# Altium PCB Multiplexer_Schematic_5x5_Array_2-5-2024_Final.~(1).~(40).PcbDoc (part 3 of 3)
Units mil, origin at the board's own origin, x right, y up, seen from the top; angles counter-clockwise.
Board outline 7305 x 4000 mil, 8 copper layers (Loop Shield 1, Loop Trace, Loop Shield 2, GND 1, DC Signal 1, DC Signal 2, GND 2 (RF), RF), stack 74.018 mil thick; 89 components, 122 nets, 436 pads, 3654 vias.
Unrouted connection lines stored in the file: 2.
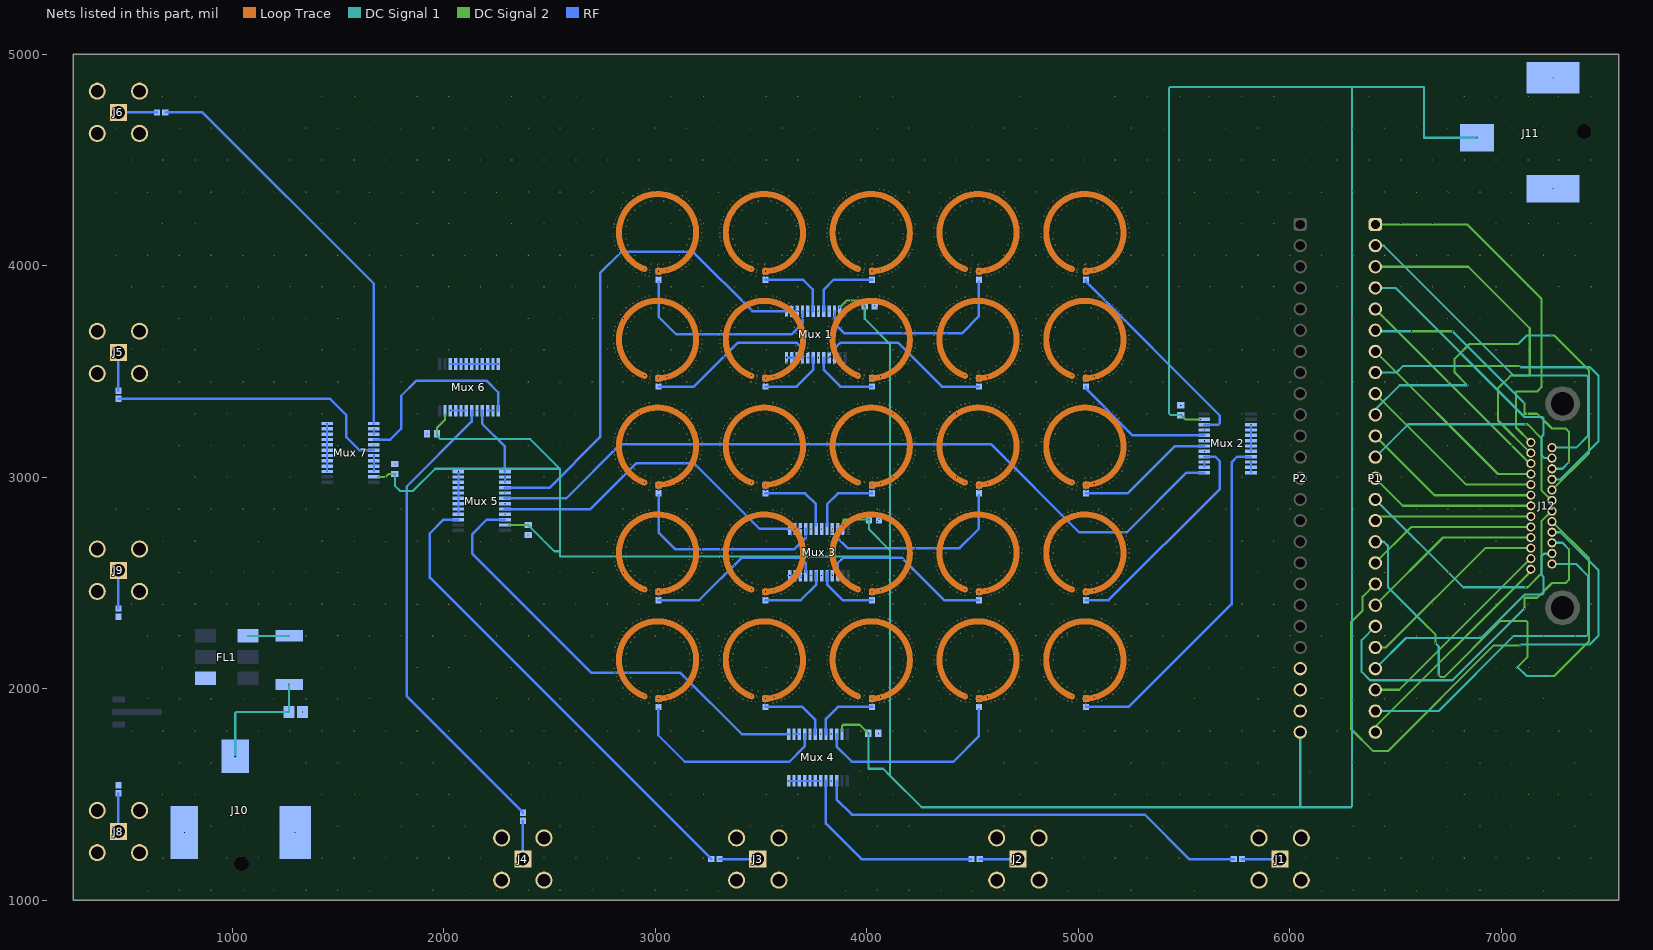
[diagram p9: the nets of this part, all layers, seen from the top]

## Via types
v1: diameter 6, hole 4, Loop Shield 1 to Loop Shield 2, 2300 vias
v2: diameter 6, hole 4, GND 2 (RF) to RF, 1131 vias
v3: diameter 6, hole 4, Loop Shield 2 to RF, 75 vias
v4: diameter 6, hole 4, DC Signal 1 to DC Signal 2, 57 vias
v5: diameter 6, hole 4, DC Signal 1 to RF, 25 vias
v6: diameter 6, hole 4, Loop Shield 2 to GND 2 (RF), 25 vias
v7: diameter 6, hole 4, Loop Trace to RF, 25 vias
v8: diameter 6, hole 4, DC Signal 2 to RF, 16 vias

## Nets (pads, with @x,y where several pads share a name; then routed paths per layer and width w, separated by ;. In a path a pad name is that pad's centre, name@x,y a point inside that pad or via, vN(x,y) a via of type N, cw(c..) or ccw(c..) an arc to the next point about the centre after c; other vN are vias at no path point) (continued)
GND: (continued)
  other v2: 450,1050 600,1050 750,1050 900,1050 1050,1050 1200,1050 1350,1050 1500,1050 1650,1050 1800,1050 1950,1050 2100,1050 2250,1050 2400,1050 2550,1050 2700,1050 2850,1050 3000,1050 3150,1050 3300,1050 3450,1050 3750,1050 3900,1050 4050,1050 4200,1050 4350,1050 4500,1050 4650,1050 4950,1050 5100,1050 5250,1050 5400,1050 5550,1050 5700,1050 6000,1050 6150,1050 6300,1050 6450,1050 6600,1050 6750,1050 6900,1050 7050,1050 7200,1050 7350,1050 675,1200 975,1200 1125,1200 1425,1200 1575,1200 1725,1200 1875,1200 2025,1200 2175,1200 2475,1200 2625,1200 2775,1200 2925,1200 3075,1200 3225,1200 3675,1200 3825,1200 4875,1200 5025,1200 5175,1200 5325,1200 5475,1200 6075,1200 6225,1200 6375,1200 6525,1200 6675,1200 6825,1200 6975,1200 7125,1200 7275,1200 7425,1200 774.92,1320.71 1298.15,1320.71 600,1350 900,1350 1050,1350 1200,1350 1500,1350 1650,1350 1800,1350 1950,1350 2100,1350 2250,1350 2550,1350 2700,1350 2850,1350 3000,1350 3150,1350 3300,1350 3450,1350 3600,1350 3750,1350 3900,1350 4050,1350 4200,1350 4350,1350 4500,1350 4650,1350 4800,1350 4950,1350 5100,1350 5250,1350 5400,1350 5550,1350 5700,1350 5850,1350 6000,1350 6150,1350 6300,1350 6450,1350 6600,1350 6750,1350 6900,1350 7050,1350 7200,1350 7350,1350 525,1500 675,1500 825,1500 975,1500 1125,1500 1275,1500 1425,1500 1575,1500 1725,1500 1875,1500 2025,1500 2175,1500 2325,1500 2475,1500 2625,1500 2775,1500 2925,1500 3075,1500 3225,1500 3375,1500 3525,1500 3675,1500 3975,1500 4125,1500 4275,1500 4425,1500 4575,1500 4725,1500 4875,1500 5025,1500 5175,1500 5325,1500 5475,1500 5625,1500 5775,1500 5925,1500 6075,1500 6225,1500 6375,1500 6525,1500 6675,1500 6825,1500 6975,1500 7125,1500 7275,1500 7425,1500 3832.99,1564.76 600,1650 750,1650 900,1650 1200,1650 1350,1650 1500,1650 1650,1650 1800,1650 1950,1650 2100,1650 2250,1650 2400,1650 2550,1650 2700,1650 2850,1650 3000,1650 3750,1650 3900,1650 4500,1650 4650,1650 4800,1650 4950,1650 5100,1650 5250,1650 5400,1650 5550,1650 5700,1650 5850,1650 6000,1650 6150,1650 6300,1650 6450,1650 6600,1650 6750,1650 6900,1650 7050,1650 7200,1650 7350,1650 3656.61,1785.24 3732.2,1785.24 3782.6,1785.24 3832.99,1785.24 4055.51,1788.62 525,1800 675,1800 825,1800 975,1800 1125,1800 1275,1800 1425,1800 1575,1800 1725,1800 1875,1800 2025,1800 2175,1800 2325,1800 2475,1800 2625,1800 2775,1800 2925,1800 3075,1800 3225,1800 3975,1800 4125,1800 4275,1800 4425,1800 4575,1800 4725,1800 4875,1800 5025,1800 5175,1800 5325,1800 5475,1800 5625,1800 5775,1800 5925,1800 6225,1800 6525,1800 6675,1800 6825,1800 6975,1800 7125,1800 7275,1800 7425,1800 1333.45,1890 600,1950 750,1950 900,1950 1050,1950 1200,1950 1350,1950 1500,1950 1650,1950 1800,1950 1950,1950 2100,1950 2250,1950 2400,1950 2550,1950 2700,1950 2850,1950 3150,1950 3300,1950 3450,1950 3600,1950 3750,1950 3900,1950 4200,1950 4350,1950 4650,1950 4800,1950 4950,1950 5100,1950 5400,1950 5550,1950 5700,1950 5850,1950 6000,1950 6150,1950 6300,1950 6450,1950 6600,1950 6750,1950 6900,1950 7050,1950 7200,1950 7350,1950 525,2100 675,2100 825,2100 975,2100 1125,2100 1275,2100 1425,2100 1575,2100 1725,2100 1875,2100 2025,2100 2175,2100 2325,2100 2475,2100 2625,2100 2775,2100 2925,2100 3075,2100 3225,2100 3375,2100 3525,2100 3675,2100 3825,2100 3975,2100 4125,2100 4275,2100 4425,2100 4575,2100 4725,2100 4875,2100 5025,2100 5175,2100 5325,2100 5475,2100 5625,2100 5775,2100 5925,2100 6225,2100 6525,2100 6675,2100 6825,2100 6975,2100 7125,2100 7275,2100 7425,2100 600,2250 750,2250 1350,2250 1500,2250 1650,2250 1800,2250 1950,2250 2100,2250 2250,2250 2400,2250 2700,2250 2850,2250 3000,2250 3150,2250 3300,2250 3450,2250 3600,2250 3750,2250 3900,2250 4050,2250 4200,2250 4350,2250 4500,2250 4650,2250 4800,2250 4950,2250 5100,2250 5250,2250 5400,2250 5700,2250 5850,2250 6000,2250 6150,2250 6300,2250 6450,2250 6600,2250 6750,2250 6900,2250 7050,2250 7200,2250 7350,2250 525,2400 675,2400 825,2400 975,2400 1125,2400 1275,2400 1425,2400 1575,2400 1725,2400 1875,2400 2025,2400 2175,2400 2325,2400 2475,2400 2625,2400 2775,2400 2925,2400 3225,2400 3375,2400 3825,2400 4125,2400 4275,2400 4575,2400 4725,2400 4875,2400 5175,2400 5325,2400 5475,2400 5625,2400 5775,2400 5925,2400 6225,2400 6525,2400 6675,2400 6825,2400 6975,2400 7125,2400 7425,2400 3737.2,2534.76 3787.6,2534.76 3837.99,2534.76 600,2550 750,2550 900,2550 1050,2550 1200,2550 1350,2550 1500,2550 1650,2550 1800,2550 2100,2550 2400,2550 2550,2550 2700,2550 2850,2550 3000,2550 3150,2550 3300,2550 3450,2550 3600,2550 4050,2550 4200,2550 4350,2550 4500,2550 4650,2550 4800,2550 4950,2550 5100,2550 5400,2550 5550,2550 5700,2550 5850,2550 6000,2550 6150,2550 6300,2550 6450,2550 6600,2550 6750,2550 6900,2550 7050,2550 7200,2550 7350,2550 525,2700 675,2700 825,2700 975,2700 1125,2700 1275,2700 1425,2700 1575,2700 1725,2700 1875,2700 2025,2700 2175,2700 2325,2700 2475,2700 2625,2700 2775,2700 2925,2700 3225,2700 3375,2700 3525,2700 3825,2700 3975,2700 4125,2700 4275,2700 4425,2700 4575,2700 4725,2700 4875,2700 5025,2700 5175,2700 5325,2700 5475,2700 5625,2700 5775,2700 5925,2700 6225,2700 6525,2700 6675,2700 6825,2700 6975,2700 7275,2700 7425,2700 2400,2726.38 3737.2,2755.24 3787.6,2755.24 3837.99,2755.24 4058.62,2800 2290.24,2824.38 450,2850 600,2850 750,2850 900,2850 1050,2850 1200,2850 1350,2850 1500,2850 1650,2850 1800,2850 1950,2850 2850,2850 3150,2850 3300,2850 3450,2850 3600,2850 3900,2850 4050,2850 4200,2850 4350,2850 4500,2850 4650,2850 4800,2850 4950,2850 5100,2850 5250,2850 5400,2850 5700,2850 5850,2850 6000,2850 6150,2850 6300,2850 6450,2850 6600,2850 6750,2850 6900,2850 7050,2850 7200,2850 7350,2850 2290.24,2874.77 2290.24,2925.17 525,3000 675,3000 825,3000 975,3000 1125,3000 1275,3000 1575,3000 1725,3000 2025,3000 2175,3000 2475,3000 2625,3000 2775,3000 2925,3000 3075,3000 3375,3000 3675,3000 3825,3000 3975,3000 4125,3000 4275,3000 4425,3000 4575,3000 4875,3000 5175,3000 5625,3000 5775,3000 5925,3000 6225,3000 6525,3000 6675,3000 6825,3000 6975,3000 7275,3000 7425,3000 1770,3062.24 5596.47,3122.2 450,3150 600,3150 750,3150 900,3150 1050,3150 1200,3150 1350,3150 1500,3150 1800,3150 1950,3150 2100,3150 2250,3150 2400,3150 2550,3150 4650,3150 4800,3150 4950,3150 5100,3150 5250,3150 5400,3150 5700,3150 6000,3150 6150,3150 6300,3150 6450,3150 6600,3150 6750,3150 6900,3150 7050,3150 7200,3150 7350,3150 1670.24,3152.8 5596.47,3172.6 1921.38,3205 5596.47,3222.99 525,3300 675,3300 825,3300 975,3300 1125,3300 1275,3300 1425,3300 1575,3300 1725,3300 1875,3300 2325,3300 2475,3300 2625,3300 2775,3300 2925,3300 3075,3300 3225,3300 3375,3300 3525,3300 3675,3300 3825,3300 3975,3300 4125,3300 4275,3300 4425,3300 4575,3300 4725,3300 4875,3300 5025,3300 5325,3300 5775,3300 5925,3300 6225,3300 6525,3300 6675,3300 6825,3300 6975,3300 7125,3300 7425,3300 2157.8,3314.76 5485,3340 600,3450 750,3450 900,3450 1050,3450 1200,3450 1350,3450 1500,3450 1650,3450 1800,3450 2250,3450 2400,3450 2550,3450 2700,3450 2850,3450 3150,3450 3300,3450 3450,3450 3600,3450 3750,3450 3900,3450 4200,3450 4650,3450 4800,3450 4950,3450 5100,3450 5250,3450 5400,3450 5550,3450 5700,3450 5850,3450 6000,3450 6150,3450 6300,3450 6450,3450 6600,3450 6750,3450 6900,3450 7050,3450 7200,3450 7350,3450 2258.58,3535.52 3722.2,3564.76 3772.6,3564.76 3822.99,3564.76 525,3600 675,3600 825,3600 975,3600 1125,3600 1275,3600 1425,3600 1575,3600 1725,3600 1875,3600 2025,3600 2175,3600 2325,3600 2475,3600 2625,3600 2775,3600 2925,3600 3075,3600 3225,3600 3525,3600 3975,3600 4125,3600 4275,3600 4425,3600 4575,3600 4725,3600 4875,3600 5025,3600 5175,3600 5325,3600 5475,3600 5625,3600 5775,3600 5925,3600 6225,3600 6525,3600 6675,3600 6825,3600 6975,3600 7125,3600 7275,3600 7425,3600 450,3750 600,3750 750,3750 900,3750 1050,3750 1200,3750 1350,3750 1500,3750 1650,3750 1800,3750 1950,3750 2100,3750 2250,3750 2400,3750 2550,3750 2700,3750 2850,3750 3150,3750 3300,3750 3450,3750 3600,3750 4050,3750 4200,3750 4350,3750 4650,3750 4800,3750 4950,3750 5100,3750 5250,3750 5400,3750 5550,3750 5700,3750 5850,3750 6000,3750 6150,3750 6300,3750 6450,3750 6600,3750 6750,3750 6900,3750 7050,3750 7200,3750 7350,3750 3722.2,3785.24 3772.6,3785.24 3822.99,3785.24 4038.62,3810 525,3900 675,3900 825,3900 975,3900 1125,3900 1275,3900 1425,3900 1575,3900 1725,3900 1875,3900 2025,3900 2175,3900 2325,3900 2475,3900 2625,3900 2775,3900 2925,3900 3075,3900 3225,3900 3375,3900 3525,3900 3675,3900 3975,3900 4125,3900 4275,3900 4425,3900 4575,3900 4725,3900 4875,3900 5025,3900 5175,3900 5325,3900 5475,3900 5625,3900 5775,3900 5925,3900 6225,3900 6525,3900 6675,3900 6825,3900 6975,3900 7125,3900 7275,3900 7425,3900 450,4050 600,4050 750,4050 900,4050 1050,4050 1200,4050 1350,4050 1500,4050 1650,4050 1800,4050 1950,4050 2100,4050 2250,4050 2400,4050 2550,4050 2700,4050 3300,4050 3450,4050 3600,4050 3750,4050 3900,4050 4050,4050 4200,4050 4350,4050 4500,4050 4650,4050 4800,4050 4950,4050 5100,4050 5250,4050 5400,4050 5550,4050 5700,4050 5850,4050 6000,4050 6150,4050 6300,4050 6450,4050 6600,4050 6750,4050 6900,4050 7050,4050 7200,4050 7350,4050 525,4200 675,4200 825,4200 975,4200 1125,4200 1275,4200 1425,4200 1575,4200 1725,4200 1875,4200 2025,4200 2175,4200 2325,4200 2475,4200 2625,4200 2775,4200 2925,4200 3075,4200 3225,4200 3375,4200 3525,4200 3675,4200 3825,4200 3975,4200 4125,4200 4275,4200 4425,4200 4575,4200 4725,4200 4875,4200 5025,4200 5175,4200 5325,4200 5475,4200 5625,4200 5775,4200 5925,4200 6225,4200 6525,4200 6675,4200 6825,4200 6975,4200 7125,4200 7275,4200 7425,4200 450,4350 600,4350 750,4350 900,4350 1050,4350 1200,4350 1350,4350 1500,4350 1650,4350 1800,4350 1950,4350 2100,4350 2250,4350 2400,4350 2550,4350 2700,4350 2850,4350 3000,4350 3150,4350 3300,4350 3450,4350 3600,4350 3750,4350 3900,4350 4050,4350 4200,4350 4350,4350 4500,4350 4650,4350 4800,4350 4950,4350 5100,4350 5250,4350 5400,4350 5550,4350 5700,4350 5850,4350 6000,4350 6150,4350 6300,4350 6450,4350 6600,4350 6750,4350 6900,4350 7050,4350 7244.84,4364.84 525,4500 675,4500 825,4500 975,4500 1125,4500 1275,4500 1425,4500 1575,4500 1725,4500 1875,4500 2025,4500 2175,4500 2325,4500 2475,4500 2625,4500 2775,4500 2925,4500 3075,4500 3225,4500 3375,4500 3525,4500 3675,4500 3825,4500 3975,4500 4125,4500 4275,4500 4425,4500 4575,4500 4725,4500 4875,4500 5025,4500 5175,4500 5325,4500 5475,4500 5625,4500 5775,4500 5925,4500 6075,4500 6225,4500 6375,4500 6525,4500 6675,4500 6825,4500 6975,4500 7125,4500 7275,4500 7425,4500 450,4650 750,4650 900,4650 1050,4650 1200,4650 1350,4650 1500,4650 1650,4650 1800,4650 1950,4650 2100,4650 2250,4650 2400,4650 2550,4650 2700,4650 2850,4650 3000,4650 3150,4650 3300,4650 3450,4650 3600,4650 3750,4650 3900,4650 4050,4650 4200,4650 4350,4650 4500,4650 4650,4650 4800,4650 4950,4650 5100,4650 5250,4650 5400,4650 5550,4650 5700,4650 5850,4650 6000,4650 6150,4650 6300,4650 6450,4650 6600,4650 6750,4650 7050,4650 7200,4650 675,4800 825,4800 975,4800 1125,4800 1275,4800 1425,4800 1575,4800 1725,4800 1875,4800 2025,4800 2175,4800 2325,4800 2475,4800 2625,4800 2775,4800 2925,4800 3075,4800 3225,4800 3375,4800 3525,4800 3675,4800 3825,4800 3975,4800 4125,4800 4275,4800 4425,4800 4575,4800 4725,4800 4875,4800 5025,4800 5175,4800 5325,4800 5475,4800 5625,4800 5775,4800 5925,4800 6075,4800 6225,4800 6375,4800 6525,4800 6675,4800 6825,4800 6975,4800 7125,4800 7275,4800 7425,4800 7244.84,4888.07
  other v3: 2976.24,1960 3056.24,1960 3481.24,1960 3561.24,1960 3986.24,1960 4066.24,1960 4491.24,1960 4571.24,1960 4996.24,1960 5076.24,1960 3016.24,1987.62 3521.24,1987.62 4026.24,1987.62 4531.24,1987.62 5036.24,1987.62 2976.24,2465 3056.24,2465 3481.24,2465 3561.24,2465 3986.24,2465 4066.24,2465 4491.24,2465 4571.24,2465 4996.24,2465 5076.24,2465 3016.24,2492.62 3521.24,2492.62 4026.24,2492.62 4531.24,2492.62 5036.24,2492.62 2976.24,2970 3056.24,2970 3481.24,2970 3561.24,2970 3986.24,2970 4066.24,2970 4491.24,2970 4571.24,2970 4996.24,2970 5076.24,2970 3016.24,2997.62 3521.24,2997.62 4026.24,2997.62 4531.24,2997.62 5036.24,2997.62 2976.24,3475 3056.24,3475 3481.24,3475 3561.24,3475 3986.24,3475 4066.24,3475 4491.24,3475 4571.24,3475 4996.24,3475 5076.24,3475 3016.24,3502.62 3521.24,3502.62 4026.24,3502.62 4531.24,3502.62 5036.24,3502.62 2976.24,3980 3056.24,3980 3481.24,3980 3561.24,3980 3986.24,3980 4066.24,3980 4491.24,3980 4571.24,3980 4996.24,3980 5076.24,3980 3016.24,4007.62 3521.24,4007.62 4026.24,4007.62 4531.24,4007.62 5036.24,4007.62
  other v4: 4000,1580 6075,1580 6095,1605 3970,1610
  other v6: 3016.24,1928 3521.24,1928 4026.24,1928 4531.24,1928 5036.24,1928 3016.24,2433 3521.24,2433 4026.24,2433 4531.24,2433 5036.24,2433 3016.24,2938 3521.24,2938 4026.24,2938 4531.24,2938 5036.24,2938 3016.24,3443 3521.24,3443 4026.24,3443 4531.24,3443 5036.24,3443 3016.24,3948 3521.24,3948 4026.24,3948 4531.24,3948 5036.24,3948
NetA1_1: C39.2
NetA1_3: C40.2 FL1.4
NetC8_1: "Loop 1.1" "Loop 1.2" C8.1
  other v7: 3016.24,3973.63
NetC8_2: "Mux 1.4" C8.2 | length 959.6
  RF w11.81: C8.2@3016.24,3923.71 3016.24,3758.76 3100,3675 3644.02,3675 3697.01,3727.99 3697.01,3785.24
NetC9_1: "Loop 2.1" "Loop 2.2" C9.1
  other v7: 3521.24,3973.63
NetC9_2: "Mux 1.6" C9.2 | length 346.5
  RF w11.81: C9.2@3521.24,3933.71 3699.37,3933.71 3745.43,3887.65 3745.43,3787.2 3747.4,3785.24
NetC10_1: "Loop 3.1" "Loop 3.2" C10.1
  other v7: 4026.24,3973.63
NetC10_2: "Mux 1.8" C10.2 | length 349.7
  RF w11.81: 3797.8,3785.24 3797.8,3887.2 3844.3,3933.71 C10.2@4026.24,3933.71
NetC11_1: "Loop 4.1" "Loop 4.2" C11.1
  other v7: 4531.24,3973.63
NetC11_2: "Mux 1.10" C11.2 | length 957
  RF w11.81: 3848.19,3785.24 3848.19,3726.81 3895,3680 4450,3680 4531.24,3761.24 C11.2@4531.24,3923.71
NetC12_1: "Loop 5.1" "Loop 5.2" C12.1
  other v7: 5036.24,3973.63
NetC12_2: "Mux 2.10" C12.2 | length 1017.5
  RF w11.81: C12.2@5036.24,3933.71 5036.24,3924.43 5670,3290.67 5670,3255.11 5663.08,3248.19 5596.47,3248.19
NetC13_1: "Loop 6.1" "Loop 6.2" C13.1
  other v7: 3016.24,3468.63
NetC13_2: "Mux 1.21" C13.2 | length 820.6
  RF w11.81: C13.2@3016.24,3428.71 3183.71,3428.71 3390,3635 3670,3635 3697.01,3607.99 3697.01,3564.76
NetC14_1: "Loop 7.1" "Loop 7.2" C14.1
  other v7: 3521.24,3468.63
NetC14_2: "Mux 1.19" C14.2 | length 316
  RF w11.81: C14.2@3521.24,3428.71 3668.51,3428.71 3747.4,3507.6 3747.4,3564.76
NetC15_1: "Loop 8.1" "Loop 8.2" C15.1
  other v7: 4026.24,3468.63
NetC15_2: "Mux 1.17" C15.2 | length 318.5
  RF w11.81: 3797.8,3564.76 3797.8,3507.2 3876.29,3428.71 C15.2@4026.24,3428.71
NetC16_1: "Loop 9.1" "Loop 9.2" C16.1
  other v7: 4531.24,3468.63
NetC16_2: "Mux 1.15" C16.2 | length 823
  RF w11.81: 3848.19,3564.76 3848.19,3608.19 3875,3635 4150,3635 4356.29,3428.71 C16.2@4531.24,3428.71
NetC17_1: "Loop 10.1" "Loop 10.2" C17.1
  other v7: 5036.24,3468.63
NetC17_2: "Mux 2.8" C17.2 | length 661.7
  RF w11.81: C17.2@5036.24,3428.71 5036.24,3418.71 5257.16,3197.8 5596.47,3197.8
NetC18_1: "Loop 11.1" "Loop 11.2" C18.1
  other v7: 3016.24,2963.63
NetC18_2: "Mux 3.4" C18.2 | length 967.5
  RF w11.81: C18.2@3016.24,2913.71 3016.24,2738.76 3095,2660 3659.02,2660 3712.01,2712.99 3712.01,2755.24
NetC19_1: "Loop 12.1" "Loop 12.2" C19.1
  other v7: 3521.24,2963.63
NetC19_2: "Mux 3.6" C19.2 | length 360.8
  RF w11.81: C19.2@3521.24,2923.71 3709.37,2923.71 3760.43,2872.65 3760.43,2772.2
NetC20_1: "Loop 13.1" "Loop 13.2" C20.1
  other v7: 4026.24,2963.63
NetC20_2: "Mux 3.8" C20.2 | length 336.7
  RF w11.81: 3812.8,2770.24 3812.8,2872.2 3864.3,2923.71 C20.2@4026.24,2923.71
NetC21_1: "Loop 14.1" "Loop 14.2" C21.1
  other v7: 4531.24,2963.63
NetC21_2: "Mux 3.10" C21.2 | length 926.1
  RF w11.81: 3863.19,2755.24 3863.19,2711.81 3910,2665 4440,2665 4531.24,2756.24 C21.2@4531.24,2913.71
NetC22_1: "Loop 15.1" "Loop 15.2" C22.1
  other v7: 5036.24,2963.63
NetC22_2: "Mux 2.6" C22.2 | length 652.9
  RF w11.81: C22.2@5036.24,2923.71 5233.71,2923.71 5457.4,3147.4 5596.47,3147.4
NetC23_1: "Loop 16.1" "Loop 16.2" C23.1
  other v7: 3016.24,2458.63
NetC23_2: "Mux 3.21" C23.2 | length 835.7
  RF w11.81: C23.2@3014.08,2418.71 3208.71,2418.71 3410,2620 3685,2620 3712.01,2592.99 3712.01,2549.76
NetC24_1: "Loop 17.1" "Loop 17.2" C24.1
  other v7: 3521.24,2458.63
NetC24_2: "Mux 3.19" C24.2 | length 328.9
  RF w11.81: C24.2@3521.24,2418.71 3688.51,2418.71 3762.4,2492.6 3762.4,2534.76 3762.4,2549.76
NetC25_1: "Loop 18.1" "Loop 18.2" C25.1
  other v7: 4026.24,2458.63
NetC25_2: "Mux 3.17" C25.2 | length 301.5
  RF w11.81: 3812.8,2549.76 3812.8,2534.76 3812.8,2492.2 3886.29,2418.71 C25.2@4026.24,2418.71
NetC26_1: "Loop 19.1" "Loop 19.2" C26.1
  other v7: 4531.24,2458.63
NetC26_2: "Mux 3.15" C26.2 | length 806
  RF w11.81: 3863.19,2549.76 3863.19,2593.19 3890,2620 4165,2620 4366.29,2418.71 C26.2@4531.24,2418.71
NetC27_1: "Loop 20.1" "Loop 20.2" C27.1
  other v7: 5036.24,2458.63
NetC27_2: "Mux 2.4" C27.2 | length 1064.4
  RF w11.81: C27.2@5036.24,2418.71 5143.71,2418.71 5670,2945 5670,3075 5647.99,3097.01 5596.47,3097.01
NetC28_1: "Loop 21.1" "Loop 21.2" C28.1
  other v7: 3016.24,1953.63
NetC28_2: "Mux 4.4" C28.2 | length 956.1
  RF w11.81: C28.2@3016.24,1903.71 3015,1902.46 3015,1780 3140,1655 3635,1655 3707.01,1727.01 3707.01,1785.24
NetC29_1: "Loop 22.1" "Loop 22.2" C29.1
  other v7: 3521.24,1953.63
NetC29_2: "Mux 4.6" C29.2 | length 328.8
  RF w11.81: C29.2@3521.24,1913.71 3696.29,1913.71 3757.4,1852.6 3757.4,1785.24
NetC30_1: "Loop 23.1" "Loop 23.2" C30.1
  other v7: 4026.24,1953.63
NetC30_2: "Mux 4.8" C30.2 | length 314.2
  RF w11.81: 3807.8,1785.24 3807.8,1857.8 3863.71,1913.71 C30.2@4026.24,1913.71
NetC31_1: "Loop 24.1" "Loop 24.2" C31.1
  other v7: 4531.24,1953.63
NetC31_2: "Mux 4.10" C31.2 | length 938.9
  RF w11.81: 3858.19,1785.24 3858.19,1726.81 3930,1655 4410,1655 4531.24,1776.24 C31.2@4531.24,1903.71
NetC32_1: "Loop 25.1" "Loop 25.2" C32.1
  other v7: 5036.24,1953.63
NetC32_2: "Mux 2.21" C32.2 | length 1663.3
  RF w11.81: C32.2@5036.24,1913.71 5238.71,1913.71 5725,2400 5725,3070 5752.01,3097.01 5816.94,3097.01
NetC33_1: C33.1 J1.1 | length 180.7
  RF w11.81: C33.1@5774.29,1195 J1.1@5955,1195
NetC33_2: "Mux 4.15" C33.2 | length 2082.2
  RF w11.81: 3858.19,1564.76 3858.19,1476.81 3930,1405 5315,1405 5525,1195 C33.2@5735.71,1195
NetC34_1: C34.1 J2.1 | length 180.7
  RF w11.81: C34.1@4534.29,1195 J2.1@4715,1195
NetC34_2: "Mux 4.17" C34.2 | length 959.7
  RF w11.81: 3807.8,1564.76 3807.8,1362.2 3975,1195 C34.2@4495.71,1195
NetC35_1: C35.1 J3.1 | length 181
  RF w11.81: C35.1@3304.29,1195 J3.1@3485.32,1195
NetC35_2: "Mux 5.15" C35.2 | length 2253
  RF w11.81: 2069.76,2799.18 1999.18,2799.18 1935,2735 1935,2525.71 3256.65,1204.06 3256.65,1203.27 3264.92,1195 C35.2@3265.71,1195
NetC36_1: C36.1 J4.1 | length 180.7
  RF w11.81: J4.1@2374.67,1195 C36.1@2374.67,1375.71
NetC36_2: "Mux 6.6" C36.2 | length 2255.6
  RF w11.81: 2132.6,3314.76 2132.6,3262.6 1825,2955 1825,1964.75 2374.67,1415.08 C36.2@2374.67,1414.29
NetC37_1: C37.1 J5.1 | length 180.7
  RF w11.81: C37.1@462.6,3409.29 J5.1@462.6,3590
NetC37_2: "Mux 7.6" C37.2 | length 1369.8
  RF w11.81: C37.2@462.6,3370.71 1464.29,3370.71 1540,3295 1540,3190 1602.4,3127.6 1670.24,3127.6
NetC38_2: "Mux 7.1" C38.2 | length 1980.1
  RF w11.81: C38.2@686.89,4725 860,4725 1670.24,3914.76 1670.24,3253.58
NetC39_1: C39.1 J8.1 | length 180.7
  RF w11.81: J8.1@462.6,1325 C39.1@462.6,1505.71
NetC40_1: C40.1 J9.1 | length 180.7
  RF w11.81: C40.1@462.6,2379.29 J9.1@462.6,2560
NetFL1_1: FL1.1 R1.1 | length 195.1
  DC Signal 1 w10: v5(1075,2250) 1075.09,2250.09 1269.91,2250.09 v5(1270,2250.18)
NetJ12_1: J12.1 P1.25 | length 1074.4
  DC Signal 2 w10: P1.25@6405,1795 6405,1820 7129.08,2544.08 7129.08,2545.07 7140,2555.99 J12.1@7140,2565
NetJ12_2: J12.2 P1.23 | length 991.8
  DC Signal 2 w10: P1.23@6405,1995 6518.16,1995 7138.16,2615 J12.2@7140,2615
NetJ12_3: J12.3 P1.21 | length 929.7
  DC Signal 2 w10: P1.21@6405,2195 6455,2195 6925,2665 J12.3@7140,2665
NetJ12_4: J12.4 P1.19 | length 867.5
  DC Signal 2 w10: P1.19@6405,2395 6725,2715 J12.4@7140,2715
NetJ12_5: J12.5 P1.17 | length 805.4
  DC Signal 2 w10: P1.17@6405,2595 6575,2765 J12.5@7140,2765
NetJ12_6: J12.6 P1.15 | length 743.3
  DC Signal 2 w10: P1.15@6405,2795 6425,2815 J12.6@7140,2815
NetJ12_7: J12.7 P1.13 | length 788.8
  DC Signal 2 w10: P1.13@6405,2995 6535,2865 J12.7@7140,2865
NetJ12_8: J12.8 P1.11 | length 851
  DC Signal 2 w10: P1.11@6405,3195 6685,2915 J12.8@7140,2915
NetJ12_9: J12.9 P1.9 | length 913.1
  DC Signal 2 w10: P1.9@6405,3395 6835,2965 J12.9@7140,2965
NetJ12_10: J12.10 P1.7 | length 975.2
  DC Signal 2 w10: P1.7@6405,3595 6985,3015 J12.10@7140,3015
NetJ12_11: J12.11 P1.5 | length 1037.4
  DC Signal 2 w10: P1.5@6405,3795 7135,3065 J12.11@7140,3065
NetJ12_12: J12.12 P1.3 | length 1616.8
  DC Signal 2 w10: P1.3@6405,3995 6845,3995 7135,3705 7135,3485.86 7129.14,3480 7045,3480 6985,3420 6985,3268.16 7138.16,3115 J12.12@7140,3115
NetJ12_13: J12.13 P1.1 | length 1747.3
  DC Signal 2 w10: P1.1@6405,4195 6840,4195 7190,3845 7190,3425 7170,3405 7070,3405 7070,3235 J12.13@7140,3165
NetJ12_14: J12.14 P1.24 | length 1635.4
  DC Signal 1 w10: P1.24@6405,1895 6705,1895 7060,2250 7404.14,2250 7410,2255.86 7410,2535 7355,2590 J12.14@7240,2590 J12.14@7240,2580.99
NetJ12_15: J12.15 P1.22 | length 1176.9
  DC Signal 1 w10: P1.22@6405,2095 6550,2240 6905,2240 7110,2445 7194.14,2445 7200,2450.86 7200,2530 7190,2540 7190,2625 7203.35,2638.35 7238.35,2638.35 J12.15@7240,2640
NetJ12_16: J12.16 P1.20 | length 1702
  DC Signal 2 w10: v4(7110,2380) 7110,2430 7170,2430 7240,2500 7305,2500 7320,2515 v4(7320,2660)
  DC Signal 1 w10: P1.20@6405,2295 6340,2230 6340,2080 6380,2040 6770,2040 v4(7110,2380) ; J12.16@7240,2690 7290,2690 v4(7320,2660)
NetJ12_17: J12.17 P1.18 | length 2776.4
  DC Signal 2 w10: P1.18@6405,2495 6345,2435 6345,2370 6290,2315 6290,1810 6395,1705 6465,1705 6965,2205 v4(7090,2205)
  DC Signal 1 w10: v4(7090,2205) 7095,2210 7420,2210 7460,2250 7460,2560 7280,2740 J12.17@7240,2740
NetJ12_18: J12.18 P1.16 | length 2613.4
  DC Signal 2 w10: v4(6630,2315) 6690,2255 v4(6690,2215) ; v4(6705,2065) 6715,2055 6730,2055 6995,2320 7119.14,2320 7125,2314.14 7125,2152 v4(7073,2100) ; v4(7235,2060) 7250,2060 7415,2225 7415,2616.84 J12.18@7241.84,2790
  DC Signal 1 w10: P1.16@6405,2695 6445,2695 6465,2675 6465,2480 v4(6630,2315) ; v4(6690,2215) 6705,2200 v4(6705,2065) ; v4(7073,2100) 7080,2100 7120,2060 v4(7235,2060)
NetJ12_19: J12.19 P1.14 | length 1299
  DC Signal 2 w10: v4(7115.29,2479.71) 7124.71,2479.71 7190,2545 7190,2791.84 J12.19@7238.16,2840
  DC Signal 1 w10: P1.14@6405,2895 6820.29,2479.71 v4(7115.29,2479.71)
NetJ12_20: J12.20 P1.12 | length 1193.2
  DC Signal 2 w10: v4(7115.29,3250.29) 7124.71,3250.29 7190,3185 7190,2938.16 7238.16,2890 J12.20@7240,2890
  DC Signal 1 w10: P1.12@6405,3095 6560.29,3250.29 v4(7115.29,3250.29)
NetJ12_21: J12.21 P1.10 | length 2045
  DC Signal 2 w10: v4(6840,3435) 6780,3495 6780,3560 6850,3630 v4(7080,3630) ; v4(7235,3670) 7250,3670 7415,3505 7415,3113.16 7241.84,2940 J12.21@7240,2940
  DC Signal 1 w10: P1.10@6405,3295 6405,3320 6520,3435 v4(6840,3435) ; v4(7080,3630) 7120,3670 v4(7235,3670)
NetJ12_22: J12.22 P1.8 | length 1690.6
  DC Signal 2 w10: v4(6810,3525) v4(7090,3525)
  DC Signal 1 w10: P1.8@6405,3495 6505,3495 6535,3525 v4(6810,3525) ; v4(7090,3525) 7095,3520 7420,3520 7460,3480 7460,3170 7280,2990 J12.22@7240,2990
NetJ12_23: J12.23 P1.6 | length 1380.5
  DC Signal 2 w10: v4(6575.29,3690) v4(6770,3690) ; v4(7110,3350) 7110,3300 7170,3300 7240,3230 7305,3230 7320,3215 v4(7320,3070)
  DC Signal 1 w10: P1.6@6405,3695 6410,3690 v4(6575.29,3690) ; v4(6770,3690) v4(7110,3350) ; J12.23@7240,3040 7290,3040 v4(7320,3070)
NetJ12_24: J12.24 P1.4 | length 1284.6
  DC Signal 1 w10: P1.4@6405,3895 6500,3895 7110,3285 7194.14,3285 7200,3279.14 7200,3200 7190,3190 7190,3105 7203.35,3091.65 7238.35,3091.65 J12.24@7240,3090
NetJ12_25: J12.25 P1.2 | length 1743.1
  DC Signal 1 w10: P1.2@6405,4095 6445,4095 7060,3480 7404.14,3480 7410,3474.14 7410,3195 7355,3140 J12.25@7240,3140 J12.25@7240,3149.01
"Output Stage 1": "Mux 1.1" "Mux 5.4" | length 2363
  RF w11.81: 2290.24,2950.36 2290.6,2950 2500,2950 2740,3190 2740,3965 2840,4065 3180,4065 3459.76,3785.24 3621.42,3785.24
"Output Stage 2": "Mux 2.1" "Mux 5.6" | length 3700.3
  RF w11.81: 2290.24,2899.97 2579.97,2899.97 2835,3155 4590,3155 5005,2740 5230,2740 5511.42,3021.42 5596.47,3021.42
"Output Stage 3": "Mux 3.1" "Mux 5.8" | length 1563.7
  RF w11.81: 2290.24,2849.58 2694.58,2849.58 2910,3065 3185,3065 3494.76,2755.24 3636.42,2755.24
"Output Stage 4": "Mux 4.1" "Mux 5.10" | length 2124.4
  RF w11.81: 2290.24,2799.18 2204.18,2799.18 2135,2730 2135,2640 2700,2075 3120,2075 3409.76,1785.24 3631.42,1785.24
"Output Stage 5": "Mux 5.1" "Mux 6.4" | length 336.2
  RF w11.81: 2184.96,3312.8 2182.99,3314.76 2182.99,3252.01 2290,3145 2290.24,3145 2290.24,3025.95
"Output Stage 6": "Mux 6.1" "Mux 7.4" | length 902.7
  RF w11.81: 1670.24,3177.99 1747.99,3177.99 1800,3230 1800,3385 1870,3455 2205,3455 2258.58,3401.42 2258.58,3314.76
"Output Stage 7": C38.1 J6.1 | length 182.4
  RF w11.81: J6.1@462.6,4725 C38.1@645,4725
VCC: "Mux 1.11" "Mux 2.11" "Mux 3.11" "Mux 4.11" "Mux 5.11" "Mux 6.11" "Mux 7.11" C1.1 C2.1 C3.1 C4.1 C5.1 C6.1 C7.1 J11.1 P2.25 | length 16583.3
  DC Signal 2 w10: v8(1690,3001.61) 1726.61,3001.61 1740,3015 v5(1770,3015) ; v5(1968.62,3205) 1968.62,3233.62 2006.61,3271.61 v8(2006.61,3295) ; v8(2310,2773.99) 2399.64,2773.99 v5@2400,2773.62 ; v8@3875,3805 3905,3835 3965.03,3835 3990.03,3810 v5(3991.38,3810) ; v8(3883.39,1800) 3883.39,1824.14 3889.24,1830 3966.88,1830 v5(4008.26,1788.62) ; v8(3888.39,2773.76) 3888.39,2792.28 3896.1,2800 v5(4011.38,2800) ; v5@5485,3295 5506.61,3273.39 v8@5575,3273.39
  DC Signal 1 w10: v5(1770,3015) 1770,2960 1795,2935 1855,2935 1960,3040 2550,3040 ; v5(1968.62,3205) 1969.58,3204.04 1969.58,3195.42 1985,3180 2410,3180 2550,3040 ; v5@2400,2773.62 2523.62,2650 2550,2650 2550,3040 ; 2550,2645 2550,2625 4110,2625 ; v5(3991.38,3810) 3991.38,3748.62 4110,3630 4110,2655 ; v5(4008.26,1788.62) 4008.26,1621.74 4078.26,1621.74 4110,1590 ; v5(4011.38,2800) 4011.38,2753.62 4110,2655 ; v5@5485,3295 5435.86,3295 5430,3300.86 5430,4839.14 5435.86,4845 6295,4845 ; 6050,1445 P2.25@6050,1795 P2.25@6055,1790 ; v5(6885,4605) 6635,4605 6635,4845 6295,4845 ; 4110,1590 4260,1440 6050,1440 6289.14,1440 6295,1445.86 6295,4845 ; 4110,1590 4110,2625 ; 4110,2625 4110,2655
  other v5: 2399.82,2773.8 5485.4,3293.31
  other v8: 5578,3273.39 3873.39,3805
"VCC Amplifier (12 V)": C41.1 J10.1 R1.2 | length 591
  DC Signal 1 w10: v5(1015.08,1680.55) 1015,1680.63 1015,1884.14 1020.86,1890 v5(1270,1890) v5(1270,2020)
pads on no net: A1.GND1 A1.IN A1.OUT FL1.2 FL1.3 FL1.5 FL1.6 J10. J11. J12.MH1 J12.MH2
copper on no net: | length 1131.3
  RF w11.81: 462.6,1544.29 462.6,1830.16 ; 462.6,2340.71 462.6,1949.84 463.39,1949.06 478.94,1949.06 579.88,2050 875,2050
  other v2: 550,1890

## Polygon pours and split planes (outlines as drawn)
GND on Loop Shield 2 "GND_L03_P128" (solid, pour order 128): 3000.06,4387.28 ccw(c3011.72,4156.22) 3023.38,4387.28 3023.38,4296.13 cw(c3011.72,4156.22) 3000.06,4296.13
GND on Loop Shield 2 "GND_L03_P138" (solid, pour order 138): 3505.06,4387.27 ccw(c3516.73,4156.22) 3528.39,4387.27 3528.39,4296.12 cw(c3516.72,4156.22) 3505.06,4296.12
GND on Loop Shield 2 "GND_L03_P139" (solid, pour order 139): 4010.06,4387.27 ccw(c4021.73,4156.22) 4033.39,4387.27 4033.39,4296.12 cw(c4021.72,4156.22) 4010.06,4296.12
GND on Loop Shield 2 "GND_L03_P140" (solid, pour order 140): 4515.06,4387.27 ccw(c4526.73,4156.22) 4538.39,4387.27 4538.39,4296.12 cw(c4526.72,4156.22) 4515.06,4296.12
GND on Loop Shield 2 "GND_L03_P142" (solid, pour order 142): 5020.06,4387.27 ccw(c5031.73,4156.22) 5043.39,4387.27 5043.39,4296.12 cw(c5031.72,4156.22) 5020.06,4296.12
GND on Loop Shield 2 "GND_L03_P143" (solid, pour order 143): 3000.06,3882.28 ccw(c3011.72,3651.22) 3023.38,3882.28 3023.38,3791.13 cw(c3011.72,3651.22) 3000.06,3791.13
GND on Loop Shield 2 "GND_L03_P144" (solid, pour order 144): 3505.06,3882.28 ccw(c3516.72,3651.22) 3528.38,3882.28 3528.38,3791.13 cw(c3516.72,3651.22) 3505.06,3791.13
GND on Loop Shield 2 "GND_L03_P145" (solid, pour order 145): 4010.06,3882.28 ccw(c4021.72,3651.22) 4033.38,3882.28 4033.38,3791.13 cw(c4021.72,3651.22) 4010.06,3791.13
GND on Loop Shield 2 "GND_L03_P146" (solid, pour order 146): 4515.06,3882.28 ccw(c4526.72,3651.22) 4538.38,3882.28 4538.38,3791.13 cw(c4526.72,3651.22) 4515.06,3791.13
GND on Loop Shield 2 "GND_L03_P147" (solid, pour order 147): 5020.06,3882.28 ccw(c5031.72,3651.22) 5043.38,3882.28 5043.38,3791.13 cw(c5031.72,3651.22) 5020.06,3791.13
GND on Loop Shield 2 "GND_L03_P148" (solid, pour order 148): 3000.06,3377.28 ccw(c3011.72,3146.22) 3023.38,3377.28 3023.38,3286.13 cw(c3011.72,3146.22) 3000.06,3286.13
GND on Loop Shield 2 "GND_L03_P149" (solid, pour order 149): 3505.06,3377.28 ccw(c3516.72,3146.22) 3528.38,3377.28 3528.38,3286.13 cw(c3516.72,3146.22) 3505.06,3286.13
GND on Loop Shield 2 "GND_L03_P150" (solid, pour order 150): 4010.06,3377.28 ccw(c4021.72,3146.22) 4033.38,3377.28 4033.38,3286.13 cw(c4021.72,3146.22) 4010.06,3286.13
GND on Loop Shield 2 "GND_L03_P151" (solid, pour order 151): 4515.06,3377.28 ccw(c4526.72,3146.22) 4538.38,3377.28 4538.38,3286.13 cw(c4526.72,3146.22) 4515.06,3286.13
GND on Loop Shield 2 "GND_L03_P152" (solid, pour order 152): 5020.06,3377.28 ccw(c5031.72,3146.22) 5043.38,3377.28 5043.38,3286.13 cw(c5031.72,3146.22) 5020.06,3286.13
GND on Loop Shield 2 "GND_L03_P155" (solid, pour order 155): 3000.06,2872.28 ccw(c3011.72,2641.22) 3023.38,2872.28 3023.38,2781.13 cw(c3011.72,2641.22) 3000.06,2781.13
GND on Loop Shield 2 "GND_L03_P157" (solid, pour order 157): 4010.06,2872.28 ccw(c4021.72,2641.22) 4033.38,2872.28 4033.38,2781.13 cw(c4021.72,2641.22) 4010.06,2781.13
GND on Loop Shield 2 "GND_L03_P158" (solid, pour order 158): 4515.06,2872.28 ccw(c4526.72,2641.22) 4538.38,2872.28 4538.38,2781.13 cw(c4526.72,2641.22) 4515.06,2781.13
GND on Loop Shield 2 "GND_L03_P159" (solid, pour order 159): 5020.06,2872.28 ccw(c5031.72,2641.22) 5043.38,2872.28 5043.38,2781.13 cw(c5031.72,2641.22) 5020.06,2781.13
GND on Loop Shield 2 "GND_L03_P160" (solid, pour order 160): 3000.06,2367.28 ccw(c3011.72,2136.22) 3023.38,2367.28 3023.38,2276.13 cw(c3011.72,2136.22) 3000.06,2276.13
GND on Loop Shield 2 "GND_L03_P161" (solid, pour order 161): 3505.06,2367.28 ccw(c3516.72,2136.22) 3528.38,2367.28 3528.38,2276.13 cw(c3516.72,2136.22) 3505.06,2276.13
GND on Loop Shield 2 "GND_L03_P162" (solid, pour order 162): 4010.06,2367.28 ccw(c4021.72,2136.22) 4033.38,2367.28 4033.38,2276.13 cw(c4021.72,2136.22) 4010.06,2276.13
GND on Loop Shield 2 "GND_L03_P163" (solid, pour order 163): 4515.06,2367.28 ccw(c4526.72,2136.22) 4538.38,2367.28 4538.38,2276.13 cw(c4526.72,2136.22) 4515.06,2276.13
GND on Loop Shield 2 "GND_L03_P164" (solid, pour order 164): 5020.06,2367.28 ccw(c5031.72,2136.22) 5043.38,2367.28 5043.38,2276.13 cw(c5031.72,2136.22) 5020.06,2276.13
GND on Loop Shield 2 "GND_L03_P166" (solid, pour order 166): 3505.06,2872.28 ccw(c3516.72,2641.22) 3528.38,2872.28 3528.38,2781.13 cw(c3516.72,2641.22) 3505.06,2781.13
GND on RF "GND_L08_P182" (solid, pour order 182): 7530,4975 294.94,4975 299.94,1024.94 7530,1024.94
GND on GND 1 "GND_L04_P180" (solid, pour order 180): 7530,4975 294.94,4975 299.94,1024.94 7530,1024.94
GND on GND 2 (RF) "GND_L07_P096" (solid, pour order 96): 7530,4975 294.94,4975 299.94,1024.94 7530,1024.94
GND on DC Signal 2 "GND_L06_P183" (solid, pour order 183): 7530,4975 294.94,4975 299.94,1024.94 7530,1024.94
GND on DC Signal 1 "GND_L05_P181" (solid, pour order 181): 7530,4975 294.94,4975 299.94,1024.94 7530,1024.94

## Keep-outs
Keep-Out Layer:
  lines w47.24: 270,1000 270,5000 7555,5000 7555,1000 270,1000

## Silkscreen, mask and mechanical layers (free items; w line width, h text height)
Mechanical 2:
  circle w1: c3016.24,3973.63 r36.56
